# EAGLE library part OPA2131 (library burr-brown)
General Purpose FET-Input Operational Amplifiers Product Folder:OPA2131
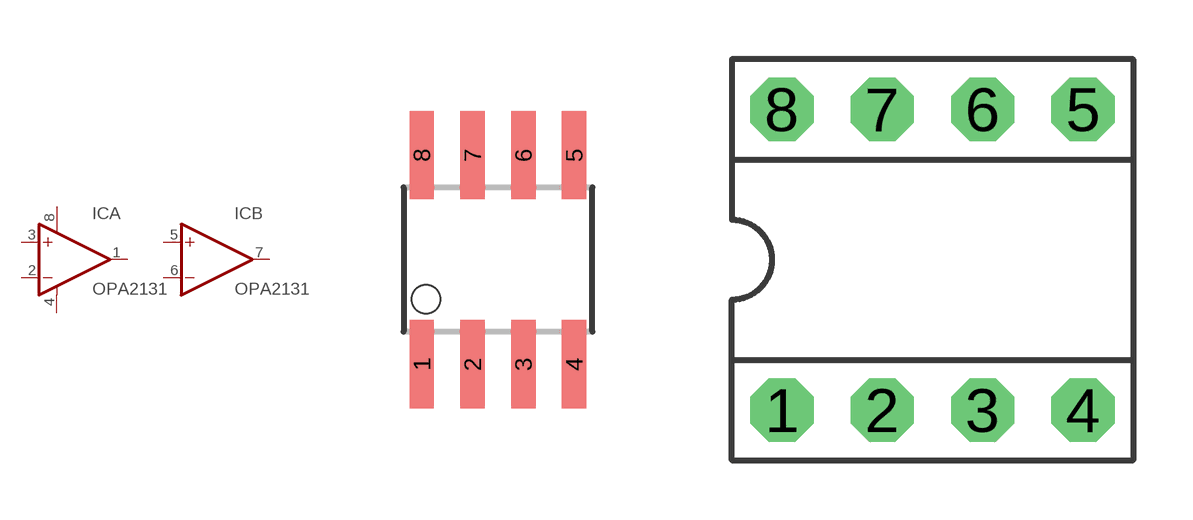
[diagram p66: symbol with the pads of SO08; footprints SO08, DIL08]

Designator prefix IC; gates A=OP-AMP+- B=OP-AMP

## OPA2131U (MF: TEXAS INSTRUMENT CONNECTORS; MPN: OPA2131UJ/2K5; OC_FARNELL: 1575488; OC_NEWARK: 75C4620)  [SO08]
1  A:OUT  out
2  A:-IN  in
3  A:+IN  in
4  A:V-  pwr
5  B:+IN  in
6  B:-IN  in
7  B:OUT  out
8  A:V+  pwr

## OPA2131P (OC_FARNELL: unknown; OC_NEWARK: unknown)  [DIL08]
Pads as for SO08

## Footprint SO08 (pad centres in mm)
Small Outline Package
smd 0.61 x 2.21: 1 -1.905,-2.616; 2 -0.635,-2.616; 3 0.635,-2.616; 4 1.905,-2.616; 5 1.905,2.616; 6 0.635,2.616; 7 -0.635,2.616; 8 -1.905,2.616

## Footprint DIL08 (pad centres in mm)
Dual In Line
drill 0.813 pad 1.6 octagon: 1 -3.81,-3.81; 2 -1.27,-3.81; 3 1.27,-3.81; 4 3.81,-3.81; 5 3.81,3.81; 6 1.27,3.81; 7 -1.27,3.81; 8 -3.81,3.81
